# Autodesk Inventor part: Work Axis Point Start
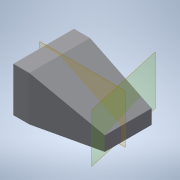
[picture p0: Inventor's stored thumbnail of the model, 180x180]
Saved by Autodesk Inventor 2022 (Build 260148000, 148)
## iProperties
Created: 2013-12
Part Number: Work Axis Point Start
Material: Generic
Document SubType Name: Modeling
Designer: John
Density: 1 g/cm^3
Appearance: Default
Author: John
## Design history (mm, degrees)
sketch "Sketch1"
  geometry: L1 (0, 0)-(32.462, 0); L2 (32.462, 0)-(32.462, 18.608); L3 (32.462, 18.608)-(0, 18.608); L4 (0, 18.608)-(0, 0)
  constraints: 8 end point, 2 parallel, 1 horizontal, 1 perpendicular
extrude "Extrusion1" new body sketch "Sketch1" distance "d0" = 25.4; taper "d1" = 0 deg
sketch "Sketch2"
  geometry: L1 (32.462, 0)-(32.462, 18.608) reference; L2 (32.462, 18.608)-(0, 18.608) reference; L3 (6.713, 18.608)-(32.462, 6.014)
  constraints: 2 end point, 2 point on line
extrude "Extrusion2" cut sketch "Sketch2" extent not by distance; stored distance "d2" = 25.4; taper "d3" = 0 deg
sketch "Sketch3"
  geometry: L1 (32.462, 0)-(32.462, 25.4) reference; L2 (0, 25.4)-(32.462, 25.4) reference; L3 (6.713, 25.4)-(6.713, 0) reference; L4 (6.713, 25.4)-(32.462, 19.575)
  constraints: 2 end point, 1 point on line
extrude "Extrusion3" cut sketch "Sketch3" extent not by distance; stored distance "d4" = 25.4; taper "d5" = 0 deg
workplane "Work Plane1"
workplane "Work Plane2"
body "Solid1"
other parameters: "d6" = 90 deg
